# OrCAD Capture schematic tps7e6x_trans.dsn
size A; title: TPS7E6750 Transient Model; rev: 1; note: Datasheet: SLVSJH7A
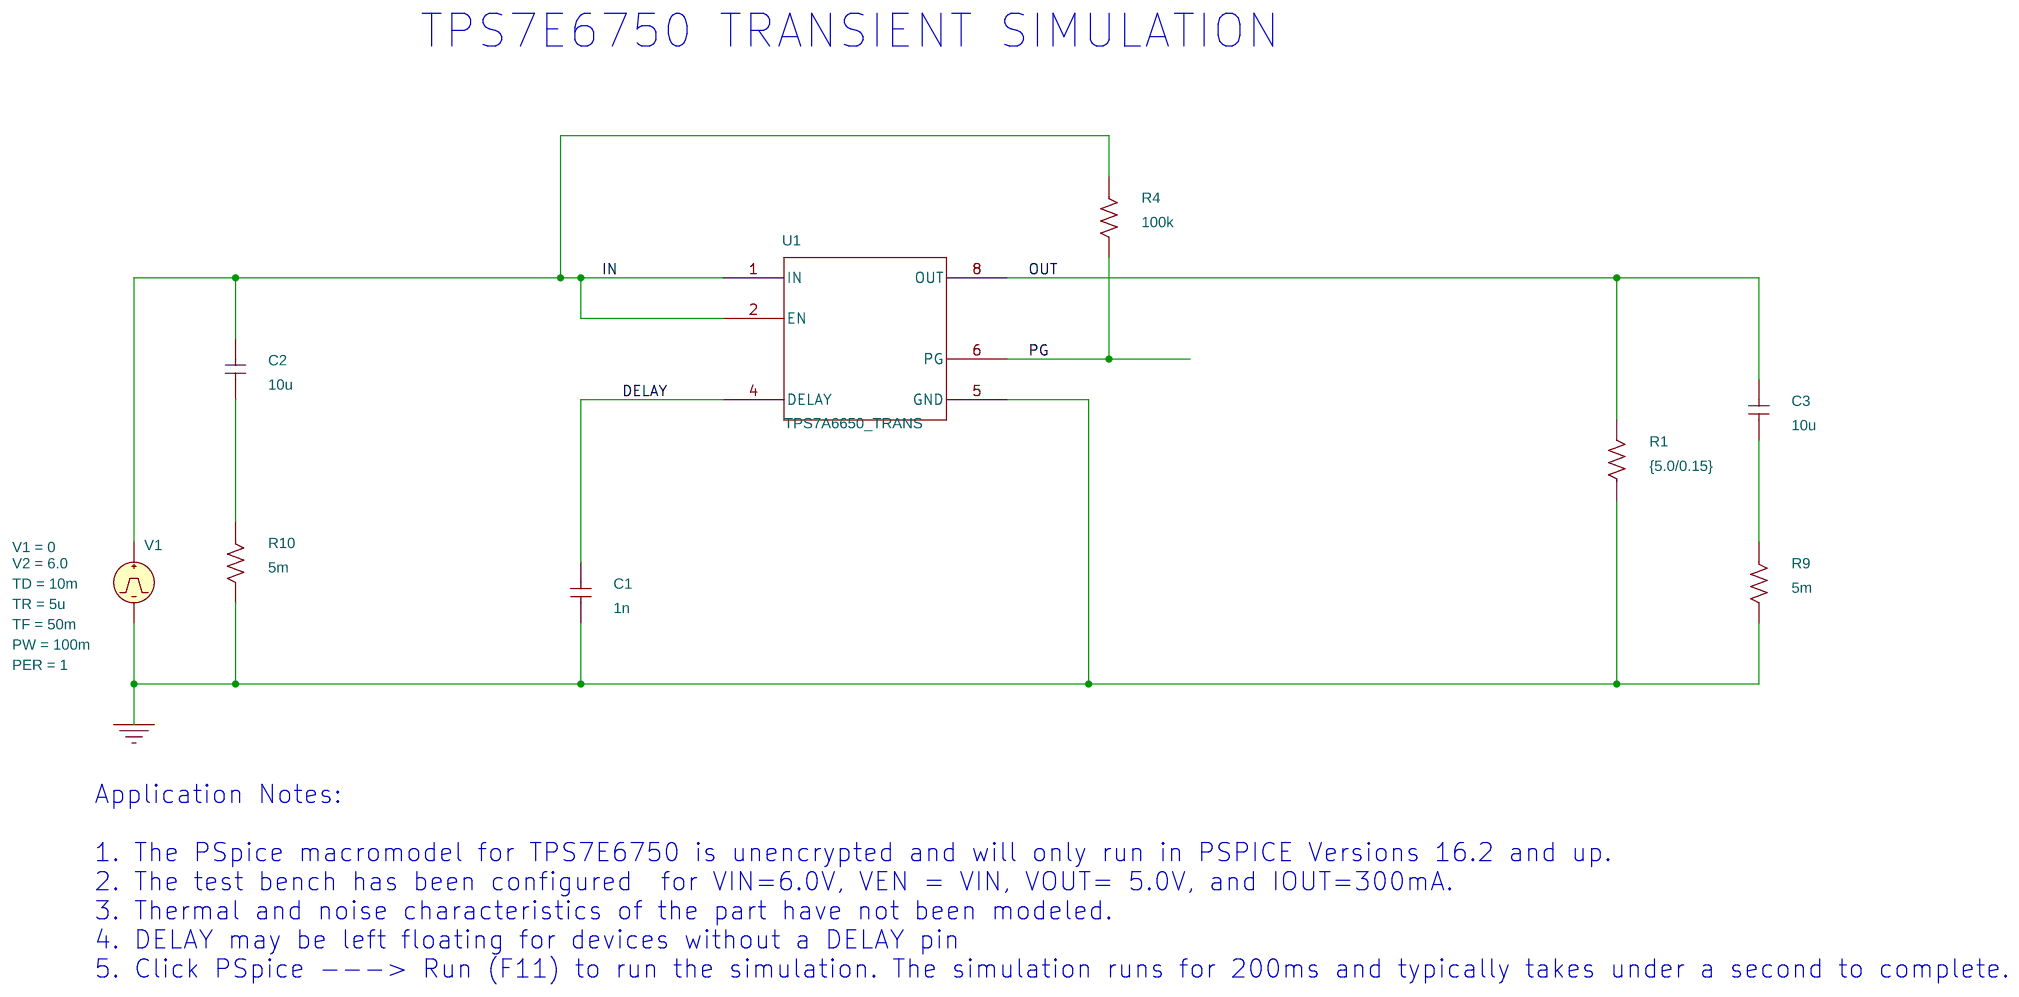
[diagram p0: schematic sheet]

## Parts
C1  1n  [RAD/CK05]
C2  10u  [RAD/CK05]
C3  10u  [RAD/CK05]
R1  {5.0/0.15}  [AX/RC05]
R4  100k  [AX/RC05]
R9  5m  [AX/RC05]
R10  5m  [AX/RC05]
U1  TPS7A6650_TRANS
V1  VPULSE

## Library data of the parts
C1-C3 = C
R1 R4 R9 R10 = R
U1 = TPS7E6650_TRANS
V1 = VPULSE: PER: 1; PW: 100m; TD: 10m; TF: 50m; TR: 5u; V1: 0; V2: 6.0

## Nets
0: C1.1 R1.1 R9.2 R10.2 U1.5(GND) V1.2(-)
DELAY: C1.2 U1.4(DELAY)
IN: C2.2 R4.1 U1.1(IN) U1.2(EN) V1.1(+)
OUT: C3.2 R1.2 U1.8(OUT)
PG: R4.2 U1.6(PG)
N944978: C2.1 R10.1
N945042: C3.1 R9.1

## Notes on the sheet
- TPS7E6750 TRANSIENT SIMULATION
- Application Notes:
  1. The PSpice macromodel for TPS7E6750 is unencrypted and will only run in PSPICE Versions 16.2 and up.
  2. The test bench has been configured  for VIN=6.0V, VEN = VIN, VOUT= 5.0V, and IOUT=300mA.
  3. Thermal and noise characteristics of the part have not been modeled.
  4. DELAY may be left floating for devices without a DELAY pin
  5. Click PSpice ---> Run (F11) to run the simulation. The simulation runs for 200ms and typically takes under a second to complete.
